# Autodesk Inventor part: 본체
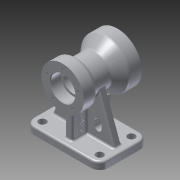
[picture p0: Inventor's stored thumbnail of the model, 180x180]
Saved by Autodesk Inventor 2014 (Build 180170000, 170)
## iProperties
Created: 2015-08
Part Number: 본체
Material: 알루미늄 6061
Document SubType Name: Modeling
Designer: aapexcom
Density: 2.71 g/cm^3
Appearance: 알루미늄 - 평지
Mass: 1061.47 g
Surface Area: 756.971 cm^2
Volume: 391.687 cm^3
Author: aapexcom
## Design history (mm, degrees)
sketch "스케치1"
  geometry: L1 (61, -40)-(-61, -40); L2 (-61, -40)-(-61, 40); L3 (-61, 40)-(61, 40); L4 (61, 40)-(61, -40); L5 (61, -40)-(-61, 40); L6 (-61, -40)-(61, 40); 1 further point
  constraints: 12 end point, 2 midpoint, 2 parallel, 1 horizontal, 1 perpendicular
  dimensions: "d0" = 122 distance of L2.end L3.end; "d1" = 80 distance of L1.end L2.end
extrude "돌출1" new body sketch "스케치1" distance "d2" = 12; taper "d3" = 0 deg
sketch "스케치2"
  geometry: L1 (61, 12)-(-61, 12) reference; L2 (0, 0)-(0, 90); L3 (-51, 12)-(-22.61, 90); L4 (-22.61, 90)-(0, 90); L5 (-51, 12)-(0, 12); L6 (22.61, 90)-(0, 90); L7 (51, 12)-(22.61, 90); L8 (-51, 12)-(51, 12); 2 further points
  constraints: 14 end point, 4 symmetric about line, 2 perpendicular, 2 point on line, 1 midpoint
  dimensions: "d4" = 90 distance of L2.start L2.end; "d5" = 70 deg angle of L5 L3; "d6" = 10 distance of L3.start L1.end
extrude "돌출2" join sketch "스케치2" stored distance "d7" = 12; taper "d8" = 0 deg
sketch "스케치3"
  geometry: L1 (40, 12)-(-40, 12) reference; L2 (-6, 90)-(6, 90) reference; L3 (-30, 12)-(-30, 90); L4 (-30, 90)-(43.754, 90); L5 (43.754, 90)-(30, 12); L6 (-30, 12)-(30, 12); 1 further point
  constraints: 8 end point, 3 point on line, 1 parallel, 1 perpendicular
  dimensions: "d9" = 10 distance from line of L3 L1.end; "d10" = 10 distance of L1.start L5.end; "d11" = 80 deg angle of L1 L5
extrude "돌출3" join sketch "스케치3" stored distance "d12" = 12; taper "d13" = 0 deg
sketch "스케치4"
  geometry: L1 (-30, 90)-(-6, 90) reference; L2 (-40, 0)-(-40, 12) reference; L3 (-40, 90)-(50, 90); L4 (-40, 90)-(-40, 125); L5 (-40, 125)-(-20, 125); L6 (-20, 125)-(-14.804, 116); L7 (-14.804, 116)-(13.315, 116); L8 (13.315, 116)-(30, 130); L9 (30, 130)-(50, 130); L10 (50, 130)-(50, 90); 1 further point
  constraints: 16 end point, 3 parallel, 3 perpendicular, 1 collinear, 1 point on line, 1 vertical alignment
  dimensions: "d14" = 20 distance of L4.end L5.end; "d15" = 90 distance of L3.start L3.end; "d16" = 20 distance of L8.end L9.end; "d17" = 52 diameter of L7 L3; "d18" = 70 diameter of L5 L3; "d19" = 80 diameter of L9 L3; "d20" = 60 deg angle of L7 L6; "d21" = 40 deg angle of L7 L8
revolve "회전1" sketch "스케치4" stored, may be unused: angle "d22" = 90 deg
sketch "스케치5"
  geometry: L1 (50, 90)-(-40, 90); L2 (50, 90)-(30, 90); L3 (30, 64)-(50, 64); L4 (50, 64)-(50, 90); L5 (30, 90)-(-23, 90); L6 (-23, 90)-(-23, 74); L7 (-23, 74)-(27, 74); L8 (-23, 90)-(-40, 90); L9 (-40, 90)-(-40, 70); L10 (-40, 70)-(-23, 70); L11 (-23, 70)-(-23, 90); L12 (30, 64)-(30, 90); L13 (30, 90)-(27, 90); L14 (27, 90)-(27, 71); L15 (27, 71)-(30, 71); L16 (30, 71)-(30, 90); L17 (-40, 55)-(-40, 125) reference; L18 (50, 50)-(50, 130) reference; 1 further point
  constraints: 32 end point, 6 parallel, 5 perpendicular, 3 point on line, 2 midpoint, 1 horizontal
  dimensions: "d23" = 20 distance of L3.end L3.start; "d24" = 17 distance of L9.end L10.end; "d25" = 40 diameter of L10 L1; "d26" = 32 diameter of L7 L1; "d27" = 52 diameter of L3 L1; "d28" = 3 distance of L15.end L14.end; "d29" = 38 diameter of L15 L1
revolve "회전2" sketch "스케치5" stored, may be unused: angle "d30" = 90 deg
sketch "스케치6"
  geometry: L1 (-61, -40)-(61, -40) reference; L2 (61, -40)-(61, 40) reference; L3 (61, 40)-(-61, 40) reference; L4 (-61, 40)-(-61, -40) reference; L5 (0, 40)-(0, -40); L6 (-61, 0)-(61, 0); C1 r 6 at (-47, 26); C2 r 6 at (-47, -26); C3 r 6 at (47, -26); C4 r 6 at (47, 26); 1 further point
  constraints: 4 centre point, 4 end point, 4 midpoint, 3 symmetric about line, 3 other
  dimensions: "d31" = 12 diameter of C1; "d32" = 52 distance of C2.centre C1.centre; "d33" = 94 distance of C3.centre C2.centre
extrude "돌출4" cut sketch "스케치6" distance "d34" = 12; taper "d35" = 0 deg
sketch "스케치7"
  geometry: L1 (-6, 12)-(-51, 12) reference; L2 (-6, 12)-(-6, 64.702) reference; L3 (0, 0)-(0, 90); L4 (-30, 36)-(-18, 36); L5 (-18, 36)-(-18, 30); L6 (-18, 30)-(-30, 30); L7 (-30, 30)-(-30, 36); L8 (30, 36)-(18, 36); L9 (18, 36)-(18, 30); L10 (18, 30)-(30, 30); L11 (30, 30)-(30, 36); A1 r 26 centre (0, 90) between (-25.091, 83.185) and (-6, 64.702) reference; A2 r 6 centre (-24, 36) between (-30, 36) and (-24, 30); A3 r 6 centre (24, 36) between (30, 36) and (24, 30)
  constraints: 18 end point, 6 symmetric about line, 4 point on circle, 3 midpoint, 3 parallel, 2 centre point, 2 horizontal alignment, 1 horizontal, 1 perpendicular, 1 vertical, 5 other
  dimensions: "d36" = 12 distance of L5.end L6.end; "d37" = 6 distance of L4.end L5.end; "d38" = 48 distance of A3.end A2.end; "d39" = 18 distance from line of L1 A2.end
extrude "돌출5" cut sketch "스케치7" stored distance "d40" = 0; taper "d41" = 0 deg
sketch "스케치8" dims "d84" = 54
  geometry: C1 r 35 at (0, 0) reference; C2 r 20 at (0, 0) reference; 7 further points
  constraints: 1 coincident, 1 vertical alignment, 9 other
  dimensions: "d46" = 360 deg dimension on C1.centre point (0, 27) (derived)
sketch "스케치9" dims "d83" = 66
  geometry: C1 r 26 at (0, 0) reference; C2 r 40 at (0, 0) reference; 7 further points
  constraints: 2 vertical alignment, 1 coincident, 8 other
  dimensions: "d51" = 360 deg dimension on C1.centre point (0, -33) (derived)
hole "구멍1" sketch "스케치9" at (31.385, -10.198), (0, -33), (-31.385, -10.198), (-19.397, 26.698), (19.397, 26.698) diameter "d53" = 3.242; stored, may be unused: countersink angle "d57" = 90 deg, drill point angle "d59" = 118 deg; dims "d54" = 10, "d55" = 4, "d56" = 2, "d58" = 13
hole "구멍2" sketch "스케치8" diameter "d60" = 3.242; stored, may be unused: countersink angle "d64" = 90 deg, drill point angle "d66" = 118 deg; dims "d61" = 10, "d62" = 4, "d63" = 2, "d65" = 13
sketch "스케치10"
  geometry: L1 (-55.518, -30)-(-12, -30) reference; L2 (-12, -6)-(-12, -30) reference; 2 further points
  constraints: 1 other
  dimensions: "d67" = 24 distance from line of point (-36, -14) L2; "d68" = 16 distance from line of point (-36, -14) L1
feature "엠보싱1" sketch "스케치10" dims "d0" = 122, "d1" = 80, "d69" = 0.5, "d70" = 0
fillet "모깎기1" dims "d71" = 5
fillet "모깎기2" dims "d72" = 14
fillet "모깎기3" dims "d73" = 3
fillet "모깎기4" dims "d74" = 3
fillet "모깎기5" dims "d75" = 0.3
fillet "모깎기6" dims "d76" = 0.3
fillet "모깎기7" dims "d77" = 3
chamfer "모따기1" distance "d78" = 1; stored, may be unused: second distance "d79" = 2, angle "d80" = 45 deg
fillet "모깎기8" dims "d81" = 3
fillet "모깎기9" dims "d82" = 3
node "솔리드1"
